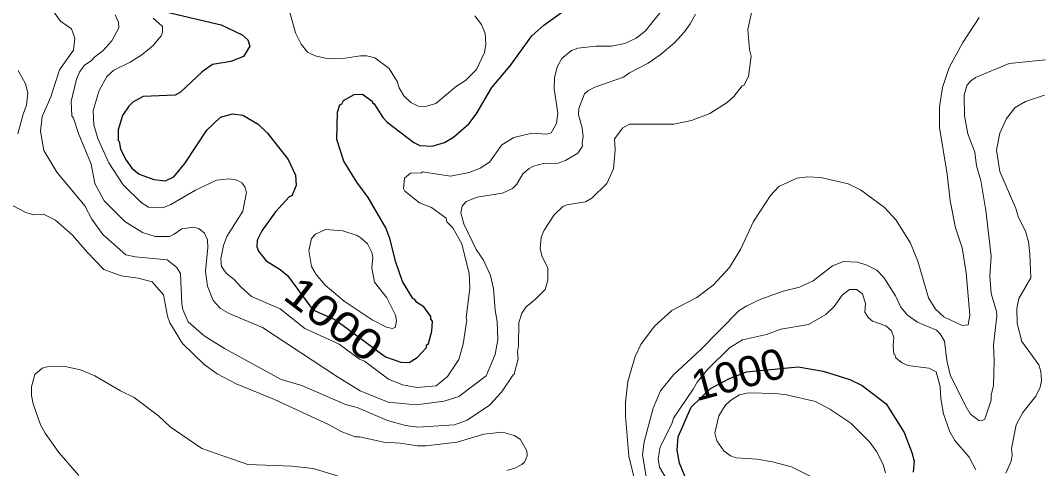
# Model space of a CAD drawing. Extents: x 447.8 to 473.9, y 7733.1 to 7760.8.
# Drawn here: x 461.927 to 464.617, y 7740.865 to 7742.044 of the extents above; entities that cross this region are included whole.
import ezdxf
from ezdxf.enums import TextEntityAlignment as Align

# ---------------------------------------------------------------- set-up
doc = ezdxf.new("R2010")
doc.units = 0
doc.header["$LTSCALE"] = 0.032
doc.layers.add('1', color=7, linetype='Continuous', lineweight=25)
doc.layers.add('2', color=7, linetype='Continuous', lineweight=13)
doc.layers.add('61', color=7, linetype='Continuous')

msp = doc.modelspace()

# ---------------------------------------------------------------- linework, layer by layer
at = {"layer": '1'}
for points in [[(462.3134, 7742.0658), (462.4551, 7742.0324), (462.5105, 7742.0055), (462.525, 7741.9928), (462.5307, 7741.9763), (462.5137, 7741.9491), (462.4808, 7741.9356), (462.4321, 7741.9281), (462.4048, 7741.9089), (462.3477, 7741.8548), (462.3337, 7741.8474), (462.2498, 7741.8434), (462.2224, 7741.8288), (462.2121, 7741.8186), (462.1953, 7741.794), (462.1839, 7741.7556), (462.1839, 7741.7283), (462.187, 7741.7252), (462.19, 7741.7054), (462.205, 7741.6758), (462.2199, 7741.6552), (462.239, 7741.6396), (462.2781, 7741.6254), (462.3083, 7741.6223), (462.3305, 7741.6326), (462.3595, 7741.6673), (462.4173, 7741.7555), (462.4533, 7741.7897), (462.4844, 7741.7984), (462.5116, 7741.7945), (462.5523, 7741.7706), (462.5767, 7741.747), (462.6313, 7741.6779), (462.6503, 7741.637), (462.6518, 7741.6092), (462.6404, 7741.5828), (462.6342, 7741.5794), (462.5979, 7741.5406), (462.5621, 7741.4905), (462.5493, 7741.4659), (462.5486, 7741.4482), (462.553, 7741.4369), (462.573, 7741.4112), (462.6103, 7741.3886), (462.6293, 7741.373), (462.696, 7741.2825), (462.7535, 7741.2571), (462.7858, 7741.2348), (462.8872, 7741.1587), (462.9277, 7741.1453), (462.9491, 7741.1439), (462.9707, 7741.1569), (462.9949, 7741.1839), (462.9952, 7741.1901), (463, 7741.1942), (463.0086, 7741.2263), (463.0102, 7741.2531), (463.0064, 7741.2583), (463.0061, 7741.2653), (462.9875, 7741.2904), (462.9697, 7741.3017), (462.9644, 7741.3095), (462.9589, 7741.3123)], [(462.8416, 7741.5781), (462.8118, 7741.618), (462.7776, 7741.6738), (462.7594, 7741.7308), (462.7609, 7741.8026), (462.7673, 7741.8215), (462.7722, 7741.8244), (462.7769, 7741.8327), (462.8046, 7741.8492), (462.827, 7741.8496), (462.8522, 7741.8312), (462.8528, 7741.8268), (462.8571, 7741.824), (462.8798, 7741.788), (462.8912, 7741.7765), (462.9618, 7741.7224), (462.9774, 7741.7144), (463.0094, 7741.7128), (463.0419, 7741.7225), (463.0661, 7741.7364), (463.1062, 7741.7718), (463.125, 7741.7972), (463.1668, 7741.8669), (463.2146, 7741.924), (463.2718, 7742.0032), (463.3035, 7742.0314), (463.3619, 7742.0732)], [(462.9589, 7741.3123), (462.9318, 7741.3568), (462.9143, 7741.4082), (462.8986, 7741.4706), (462.8876, 7741.4987), (462.8416, 7741.5781)], [(463.6764, 7740.8391), (463.6602, 7740.8791), (463.654, 7740.9132), (463.6565, 7740.9491), (463.691, 7741.0268), (463.7417, 7741.076), (463.7912, 7741.1023), (463.836, 7741.1192), (463.9716, 7741.1325), (464.0379, 7741.1213), (464.108, 7741.0994), (464.1403, 7741.0839), (464.2037, 7741.0353), (464.2502, 7740.9603), (464.271, 7740.9075), (464.2767, 7740.8847), (464.2743, 7740.8559)]]:
    msp.add_lwpolyline(points, dxfattribs=at)
at = {"layer": '2'}
for points in [[(462.9227, 7741.8664), (462.918, 7741.8834), (462.8966, 7741.9169), (462.8587, 7741.9453), (462.8382, 7741.9508), (462.821, 7741.9509), (462.7809, 7741.9445), (462.7362, 7741.9429), (462.7021, 7741.9504), (462.6824, 7741.9606), (462.6657, 7741.981), (462.6501, 7742.0108), (462.6165, 7742.1354)], [(463.2458, 7741.2739), (463.2378, 7741.249), (463.2371, 7741.1878), (463.234, 7741.1719), (463.2355, 7741.154), (463.2257, 7741.1133), (463.2225, 7741.1119), (463.1924, 7741.0661), (463.1604, 7741.0317), (463.1017, 7740.9927), (463.0687, 7740.9802), (462.9717, 7740.9745), (462.9392, 7740.9788), (462.8921, 7740.9915), (462.8126, 7741.0257), (462.7816, 7741.0334), (462.6667, 7741.0834), (462.6131, 7741.0997), (462.4637, 7741.1809), (462.41, 7741.2144), (462.3683, 7741.2508), (462.3542, 7741.2837), (462.3513, 7741.2987), (462.3481, 7741.3782), (462.3379, 7741.3951), (462.3133, 7741.4137), (462.2291, 7741.4217), (462.2045, 7741.427), (462.1443, 7741.4806), (462.1147, 7741.5214), (462.0966, 7741.5561), (462.0231, 7741.6446), (461.9884, 7741.702), (461.9803, 7741.7528), (461.9844, 7741.7909), (462.0073, 7741.8431), (462.0298, 7741.9136), (462.0667, 7741.9657), (462.07, 7741.9969), (462.0618, 7742.0213), (462.0329, 7742.0417), (462.0114, 7742.0705)], [(462.4112, 7741.4842), (462.4194, 7741.4663), (462.4203, 7741.4468), (462.4139, 7741.3836), (462.4195, 7741.3449), (462.4337, 7741.307), (462.453, 7741.2859), (462.4775, 7741.2725), (462.5637, 7741.2366), (462.761, 7741.1062), (462.8208, 7741.0695), (462.8941, 7741.0395), (462.968, 7741.033), (463.0415, 7741.0426), (463.0795, 7741.0548), (463.1515, 7741.1094), (463.1754, 7741.1655), (463.1826, 7741.2047), (463.181, 7741.2518), (463.1752, 7741.2818), (463.1712, 7741.339), (463.1634, 7741.3733), (463.1451, 7741.4131), (463.1257, 7741.4411), (463.0926, 7741.509), (463.0849, 7741.5373), (463.0884, 7741.5553), (463.0992, 7741.5676), (463.1282, 7741.5788), (463.1948, 7741.5892), (463.221, 7741.6014), (463.232, 7741.6128), (463.2478, 7741.6401), (463.2644, 7741.6547), (463.2758, 7741.6608), (463.3025, 7741.6678), (463.3412, 7741.6679), (463.3605, 7741.6751), (463.3931, 7741.6942), (463.4054, 7741.7131), (463.4038, 7741.721), (463.4071, 7741.7384), (463.4039, 7741.7613), (463.3943, 7741.795), (463.3957, 7741.8118), (463.4104, 7741.8505), (463.4192, 7741.8587), (463.4374, 7741.8685), (463.5131, 7741.8949), (463.5289, 7741.9059), (463.5772, 7741.9309), (463.6095, 7741.9529), (463.6465, 7741.985), (463.6731, 7742.0136), (463.6883, 7742.0344), (463.7021, 7742.0605)], [(463.851, 7742.0723), (463.84, 7742.0201), (463.8439, 7741.9676), (463.8486, 7741.9496), (463.8415, 7741.8961), (463.8287, 7741.8726), (463.825, 7741.8716), (463.8025, 7741.8437), (463.7852, 7741.8279), (463.7398, 7741.799), (463.6911, 7741.7805), (463.6451, 7741.7713), (463.5281, 7741.7713), (463.5106, 7741.7615), (463.489, 7741.7327), (463.4912, 7741.7036), (463.4863, 7741.6531), (463.4693, 7741.6147), (463.4297, 7741.5759), (463.4126, 7741.5665), (463.3641, 7741.5589), (463.3534, 7741.5548), (463.3303, 7741.5326), (463.3038, 7741.4923), (463.2961, 7741.4733), (463.2933, 7741.4442), (463.2982, 7741.4246), (463.314, 7741.3925)], [(463.6212, 7742.0793), (463.5695, 7742.0155), (463.5462, 7741.9967), (463.5164, 7741.9834), (463.4813, 7741.9757), (463.4401, 7741.9764), (463.3926, 7741.9708), (463.376, 7741.9649), (463.3505, 7741.9439), (463.3381, 7741.9219), (463.3317, 7741.8931), (463.3301, 7741.8636)], [(462.176, 7742.058), (462.1847, 7742.0387), (462.1861, 7742.0238), (462.168, 7741.9904), (462.1443, 7741.9634), (462.1226, 7741.9479), (462.1145, 7741.9381), (462.0944, 7741.9254), (462.0822, 7741.9078), (462.075, 7741.889), (462.0604, 7741.8305), (462.0628, 7741.7924), (462.0671, 7741.7867), (462.0799, 7741.7466), (462.113, 7741.666), (462.1232, 7741.6151), (462.1471, 7741.569), (462.2014, 7741.5148), (462.2482, 7741.4859), (462.2817, 7741.4755), (462.3188, 7741.4755)], [(463.272, 7741.7472), (463.2245, 7741.7361), (463.1932, 7741.7161), (463.1604, 7741.6706), (463.136, 7741.655), (463.1067, 7741.6434), (463.0581, 7741.6343), (462.9843, 7741.6455), (462.9819, 7741.6431), (462.9524, 7741.6424), (462.9368, 7741.6292), (462.9342, 7741.6014), (462.9378, 7741.5945), (462.976, 7741.5643), (463.0081, 7741.5515), (463.0463, 7741.5233), (463.0481, 7741.5142), (463.0638, 7741.4987), (463.0879, 7741.4559), (463.1072, 7741.3785), (463.1088, 7741.3397), (463.0993, 7741.2617), (463.1008, 7741.2564), (463.0912, 7741.1922), (463.08, 7741.1519), (463.0498, 7741.1072), (463.0199, 7741.0825), (462.9703, 7741.078), (462.9315, 7741.0858), (462.8952, 7741.1), (462.8321, 7741.1479), (462.8189, 7741.1533), (462.7652, 7741.1924), (462.6747, 7741.2333), (462.6097, 7741.2851), (462.5349, 7741.318), (462.5065, 7741.3428), (462.489, 7741.3626), (462.4679, 7741.379), (462.4563, 7741.3968), (462.454, 7741.4164), (462.461, 7741.4516), (462.4703, 7741.4753), (462.5124, 7741.5423), (462.522, 7741.592), (462.5175, 7741.6062), (462.5097, 7741.6166), (462.4974, 7741.6238), (462.476, 7741.6269), (462.4426, 7741.6239), (462.3877, 7741.5975), (462.3227, 7741.5593), (462.3019, 7741.5512), (462.2637, 7741.5527), (462.2445, 7741.5646), (462.1973, 7741.6112), (462.1596, 7741.6689), (462.1304, 7741.7334), (462.1199, 7741.769), (462.1182, 7741.807), (462.134, 7741.8591), (462.1543, 7741.8963), (462.1726, 7741.9131), (462.2162, 7741.9341), (462.2466, 7741.9535), (462.2766, 7741.9778), (462.2971, 7742.0028), (462.3008, 7742.0118), (462.3008, 7742.0274), (462.2763, 7742.05)], [(463.1218, 7742.0556), (463.1395, 7742.0331), (463.1489, 7742.009), (463.1505, 7741.9809), (463.1475, 7741.9595), (463.1266, 7741.9142), (463.0971, 7741.886), (463.0736, 7741.871), (463.0193, 7741.8251)], [(463.5445, 7740.8256), (463.5272, 7740.8979), (463.5177, 7741.003), (463.5177, 7741.039), (463.5244, 7741.0939), (463.5436, 7741.1596), (463.5587, 7741.1912), (463.5945, 7741.2396), (463.6398, 7741.2809), (463.7057, 7741.3153), (463.7483, 7741.3478), (463.7916, 7741.3943), (463.8216, 7741.443), (463.8543, 7741.5145), (463.899, 7741.5834), (463.9208, 7741.6073), (463.9687, 7741.629), (463.9972, 7741.6325), (464.0319, 7741.6302), (464.1031, 7741.614), (464.1355, 7741.5985), (464.1993, 7741.5514), (464.23, 7741.5182), (464.2674, 7741.4582), (464.2862, 7741.4109), (464.3146, 7741.314), (464.3329, 7741.2844), (464.3546, 7741.2639), (464.4027, 7741.2415), (464.4187, 7741.2434), (464.4234, 7741.2682), (464.4139, 7741.3798), (464.4035, 7741.4455), (464.3857, 7741.4987), (464.3714, 7741.5689), (464.3641, 7741.6398), (464.3434, 7741.7618), (464.3433, 7741.8169), (464.351, 7741.8676), (464.3687, 7741.9196), (464.4046, 7741.9856), (464.4479, 7742.0511)], [(464.6219, 7741.9404), (464.5264, 7741.9307), (464.4384, 7741.8934), (464.4246, 7741.8838), (464.4153, 7741.8724), (464.4083, 7741.8469), (464.4091, 7741.7931), (464.4179, 7741.7453), (464.4366, 7741.6974), (464.4407, 7741.661), (464.4524, 7741.6231), (464.4651, 7741.5439), (464.4795, 7741.4239), (464.4756, 7741.3715), (464.4796, 7741.3256), (464.4931, 7741.2783), (464.4939, 7741.2669), (464.4852, 7741.1896), (464.4875, 7741.1482), (464.4859, 7741.0839), (464.479, 7741.0585), (464.4793, 7741.0454), (464.4628, 7740.9949), (464.4544, 7740.9906), (464.4466, 7740.9913), (464.4244, 7741.0096), (464.4106, 7741.0323), (464.3719, 7741.1114), (464.363, 7741.1492), (464.3569, 7741.2005), (464.3456, 7741.2197), (464.336, 7741.2291), (464.2858, 7741.2501), (464.2595, 7741.269), (464.2419, 7741.2897), (464.2278, 7741.3191), (464.1972, 7741.3675), (464.179, 7741.3873), (464.1527, 7741.4002), (464.1281, 7741.4082), (464.0908, 7741.4097), (464.0618, 7741.3981), (464.0115, 7741.3589), (463.9755, 7741.3422), (463.9324, 7741.3316), (463.8735, 7741.3105), (463.8368, 7741.2935), (463.8172, 7741.2805), (463.715, 7741.1776), (463.6441, 7741.1121), (463.6103, 7741.0696), (463.5906, 7741.0239), (463.5675, 7740.9351), (463.5626, 7740.9011), (463.5722, 7740.8446)], [(461.9214, 7741.9116), (461.9407, 7741.8772), (461.9463, 7741.8535), (461.9431, 7741.8207), (461.9341, 7741.7974), (461.9208, 7741.7452)], [(463.0193, 7741.8251), (462.9921, 7741.817), (462.9726, 7741.8186), (462.9536, 7741.828), (462.9352, 7741.8456), (462.9227, 7741.8664)], [(463.3301, 7741.8636), (463.3397, 7741.7998), (463.3363, 7741.7722), (463.3222, 7741.7485), (463.3114, 7741.7449), (463.272, 7741.7472)], [(464.4932, 7741.7028), (464.5021, 7741.7469), (464.5201, 7741.7861), (464.5423, 7741.8147), (464.5694, 7741.8306), (464.6197, 7741.8475)], [(464.5773, 7741.4618), (464.5693, 7741.4891), (464.5511, 7741.5257), (464.5439, 7741.5494), (464.5022, 7741.646), (464.4932, 7741.7028)], [(461.9064, 7741.5568), (461.9419, 7741.5385), (461.9623, 7741.5325), (461.9876, 7741.5339), (462.0192, 7741.5182), (462.0639, 7741.4788), (462.1025, 7741.434), (462.1468, 7741.3886), (462.1924, 7741.3719), (462.2369, 7741.3663), (462.2737, 7741.3562), (462.3038, 7741.3219), (462.3138, 7741.2658), (462.3197, 7741.2481), (462.3532, 7741.1945), (462.4101, 7741.139), (462.4448, 7741.114), (462.4945, 7741.0883), (462.5949, 7741.047), (462.7392, 7740.9805), (462.7704, 7740.9624), (462.8069, 7740.9491), (462.8185, 7740.9488), (462.8826, 7740.935), (462.9253, 7740.9321), (462.9709, 7740.9248), (462.9929, 7740.9247), (463.0757, 7740.9347), (463.1453, 7740.9558), (463.1944, 7740.9606), (463.2251, 7740.9522), (463.2413, 7740.9424), (463.2585, 7740.9123), (463.2593, 7740.8991), (463.2528, 7740.8825), (463.2456, 7740.8756), (463.2275, 7740.8665), (463.2058, 7740.8604)], [(462.3188, 7741.4755), (462.3317, 7741.4813), (462.3512, 7741.4956), (462.3822, 7741.4996), (462.3964, 7741.4961), (462.4112, 7741.4842)], [(464.5182, 7740.8529), (464.5317, 7740.885), (464.5348, 7740.9004), (464.5326, 7740.9177), (464.5451, 7740.9806), (464.5628, 7741.0127), (464.5968, 7741.0552), (464.6079, 7741.079), (464.6118, 7741.0963), (464.6102, 7741.1203), (464.6046, 7741.138), (464.5604, 7741.1992), (464.5477, 7741.2464), (464.5469, 7741.2858), (464.5521, 7741.3127), (464.5835, 7741.3668), (464.5813, 7741.4298), (464.5773, 7741.4618)], [(463.314, 7741.3925), (463.314, 7741.3609), (463.3068, 7741.3359), (463.2818, 7741.3109), (463.2565, 7741.2905), (463.2458, 7741.2739)], [(463.6249, 7740.8387), (463.6074, 7740.8689), (463.6042, 7740.8907), (463.6091, 7740.9221), (463.6398, 7740.9831), (463.6443, 7740.9982), (463.696, 7741.0736), (463.7063, 7741.0928), (463.7346, 7741.1266), (463.7913, 7741.1831), (463.826, 7741.2038), (463.8884, 7741.2179), (463.9267, 7741.2319), (463.9992, 7741.2441), (464.0449, 7741.2701), (464.0662, 7741.2917), (464.0879, 7741.321), (464.1067, 7741.3359), (464.1255, 7741.3357), (464.1408, 7741.3247), (464.1491, 7741.2994), (464.147, 7741.2769), (464.156, 7741.2628), (464.1675, 7741.2529), (464.2022, 7741.2406), (464.2175, 7741.2276), (464.2238, 7741.2101), (464.2215, 7741.1887), (464.2231, 7741.1664), (464.2261, 7741.1651), (464.2284, 7741.1566), (464.2433, 7741.1443), (464.2604, 7741.1363), (464.3157, 7741.1293), (464.3346, 7741.1192), (464.3456, 7741.0809), (464.3473, 7741.0482), (464.3543, 7741.0091), (464.3707, 7740.9614), (464.3838, 7740.9392), (464.4218, 7740.8951), (464.4394, 7740.8615)], [(462.7606, 7740.8462), (462.6968, 7740.8653), (462.641, 7740.8717), (462.5254, 7740.8756), (462.4041, 7740.918), (462.3207, 7740.9751), (462.2901, 7741.0035), (462.2262, 7741.0521), (462.1904, 7741.0697), (462.1228, 7741.1091), (462.0854, 7741.1247), (462.0452, 7741.1332), (461.9979, 7741.1331), (461.984, 7741.1296), (461.9649, 7741.1124), (461.9562, 7741.0806), (461.9562, 7741.0576), (461.9609, 7741.0354), (461.9798, 7740.98), (461.9919, 7740.958), (462.028, 7740.9074), (462.0806, 7740.8468)], [(464.2015, 7740.8536), (464.195, 7740.8762), (464.1776, 7740.9099), (464.1603, 7740.9347), (464.1108, 7740.9849), (464.0553, 7741.0214), (464.0172, 7741.042), (463.9412, 7741.0594), (463.9123, 7741.0626), (463.8412, 7741.0642), (463.8173, 7741.0593), (463.7937, 7741.0444), (463.7803, 7741.0312), (463.7636, 7741.0035), (463.7533, 7740.9592), (463.7579, 7740.9382), (463.7769, 7740.9116), (463.7945, 7740.899), (463.8092, 7740.8932), (463.8636, 7740.8896), (463.9043, 7740.8831), (463.954, 7740.8701), (464.0136, 7740.84)]]:
    msp.add_lwpolyline(points, dxfattribs=at)
msp.add_lwpolyline([(462.7027, 7741.4817), (462.7293, 7741.4939), (462.7745, 7741.4906), (462.8125, 7741.4777), (462.8232, 7741.4715), (462.8396, 7741.4558), (462.8507, 7741.433), (462.8539, 7741.4201), (462.8515, 7741.3934), (462.8585, 7741.3553), (462.8906, 7741.3145), (462.9129, 7741.2685), (462.9156, 7741.2538), (462.9122, 7741.2359), (462.905, 7741.2335), (462.8895, 7741.2373), (462.8521, 7741.256), (462.7781, 7741.3053), (462.7284, 7741.3478), (462.705, 7741.3757), (462.6921, 7741.3965), (462.6858, 7741.4387), (462.6923, 7741.4701)], close=True, dxfattribs=at)

# ---------------------------------------------------------------- texts
at = {"layer": '61'}
for rotation, width, p in [(322.595, 1.2, (462.7271, 7741.2269)), (15.258, 1.05, (463.825, 7741.0747))]:
    msp.add_text('1000', height=0.08, rotation=rotation, dxfattribs=dict(at, width=width)).set_placement(p, align=Align.CENTER)

doc.saveas('drawing.dxf')
